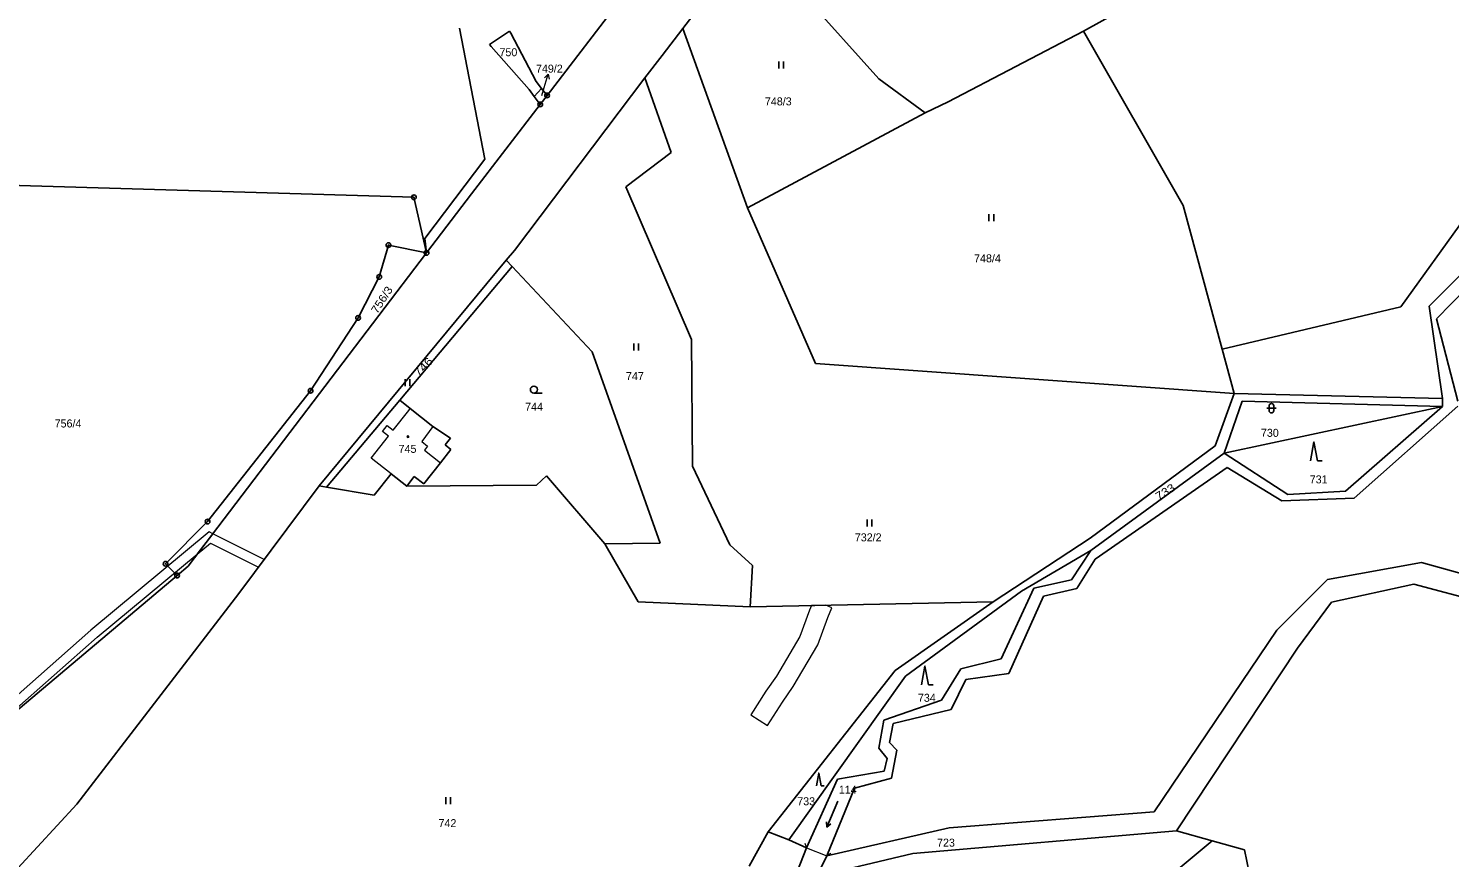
# Model space of a CAD drawing. Extents: x -727701 to -724405, y -960481 to -957284.
# Drawn here: x -726194 to -725892.1, y -958088.6 to -957912.5 of the extents above; entities that cross this region are included whole.
import ezdxf
from ezdxf.enums import TextEntityAlignment as Align

# ---------------------------------------------------------------- set-up
doc = ezdxf.new("R2010")
doc.units = 0
doc.header["$LTSCALE"] = 0.68
for name, color, linetype, lineweight in [('1', 7, 'Continuous', 25), ('13', 7, 'Continuous', 13), ('3', 7, 'Continuous', 25), ('4', 7, 'Continuous', 13), ('5', 7, 'Continuous', 25), ('7', 7, 'Continuous', 13), ('8', 7, 'Continuous', 25)]:
    doc.layers.add(name, color=color, linetype=linetype, lineweight=lineweight)
doc.layers.add('2', color=7, linetype='Continuous')

msp = doc.modelspace()

# ---------------------------------------------------------------- linework, layer by layer
at = {"layer": '1'}
for p, q in [((-726083.8, -957926.72), (-726042.74, -957873.32)), ((-725969.82, -957913.07), (-725930.41, -957891.06)), ((-726054.99, -957912.52), (-726040.19, -957893.25)), ((-726013.3, -957923.18), (-726040.19, -957893.25)), ((-726097, -957940.27), (-726102.4, -957912.45)), ((-726059.35, -957918.2), (-726054.99, -957912.52)), ((-726041.22, -957950.59), (-726054.99, -957912.52)), ((-726096.01, -957915.87), (-726091.76, -957913.04)), ((-726091.76, -957913.04), (-726091.5, -957913.52)), ((-726091.5, -957913.52), (-726086.14, -957923.75)), ((-725998.59, -957928.06), (-725969.82, -957913.07)), ((-725948.65, -957950.09), (-725969.82, -957913.07)), ((-726095.7, -957916.34), (-726096.01, -957915.87)), ((-726087.61, -957925.46), (-726095.7, -957916.34)), ((-726063, -957923), (-726059.35, -957918.2)), ((-726090.73, -957959.65), (-726063, -957923)), ((-726086.14, -957923.75), (-726084.98, -957925.28)), ((-726057.42, -957938.87), (-726063, -957923)), ((-726003.5, -957930.42), (-726013.3, -957923.18)), ((-726086.51, -957926.92), (-726087.61, -957925.46)), ((-726084.98, -957925.28), (-726086.51, -957926.92)), ((-726085.25, -957928.62), (-726086.51, -957926.92)), ((-726083.8, -957926.72), (-726085.25, -957928.62)), ((-726084.98, -957925.28), (-726083.8, -957926.72)), ((-726085.25, -957928.62), (-726099.85, -957947.6)), ((-726003.5, -957930.42), (-726041.22, -957950.59)), ((-725998.59, -957928.06), (-726003.5, -957930.42)), ((-726067.08, -957946.15), (-726057.42, -957938.87)), ((-726109.77, -957957.13), (-726097, -957940.27)), ((-726204.42, -957945.58), (-726112.08, -957948.36)), ((-726112.08, -957948.36), (-726109.41, -957960.16)), ((-726099.85, -957947.6), (-726109.41, -957960.16)), ((-726053.09, -957978.59), (-726067.08, -957946.15)), ((-726041.22, -957950.59), (-726026.78, -957983.68)), ((-725940.36, -957980.64), (-725948.65, -957950.09)), ((-725902.42, -957971.61), (-725888.74, -957952.67)), ((-726109.41, -957960.16), (-726109.77, -957957.13)), ((-726109.41, -957960.16), (-726160.05, -958026.69)), ((-726117.51, -957958.5), (-726119.45, -957965.25)), ((-726109.41, -957960.16), (-726117.51, -957958.5)), ((-726090.73, -957959.65), (-726092.46, -957961.74)), ((-725896.43, -957971.51), (-725884.9, -957959.98)), ((-726092.46, -957961.74), (-726132.25, -958009.67)), ((-726115.1, -957991.46), (-726091.22, -957963.06)), ((-726092.46, -957961.74), (-726091.22, -957963.06)), ((-726091.22, -957963.06), (-726074.22, -957981.19)), ((-725894.85, -957974.2), (-725883.57, -957962.64)), ((-726119.45, -957965.25), (-726123.94, -957973.97)), ((-725902.42, -957971.61), (-725940.36, -957980.64)), ((-725893.53, -957991.12), (-725896.43, -957971.51)), ((-726123.94, -957973.97), (-726134.05, -957989.44)), ((-725890.33, -957991.63), (-725894.85, -957974.2)), ((-726052.9, -958005.48), (-726053.09, -957978.59)), ((-726074.22, -957981.19), (-726059.78, -958021.83)), ((-725937.8, -957990.06), (-725940.36, -957980.64)), ((-726026.78, -957983.68), (-725937.8, -957990.06)), ((-726134.05, -957989.44), (-726155.91, -958017.23)), ((-725941.85, -958001.15), (-725937.8, -957990.06)), ((-725937.8, -957990.06), (-725893.53, -957991.12)), ((-725893.54, -957992.8), (-725893.53, -957991.12)), ((-726130.65, -958009.95), (-726115.1, -957991.46)), ((-726112.85, -957993.25), (-726115.1, -957991.46)), ((-726108.08, -957997.02), (-726112.85, -957993.25)), ((-725939.98, -958002.68), (-725936.1, -957991.65)), ((-725939.98, -958002.68), (-725893.54, -957992.8)), ((-725936.1, -957991.65), (-725893.54, -957992.8)), ((-725914.18, -958010.81), (-725893.54, -957992.8)), ((-725912.35, -958012.26), (-725890.34, -957992.75)), ((-726104.28, -957999.5), (-726108.08, -957997.02)), ((-726105.46, -958000.95), (-726104.28, -957999.5)), ((-726106.44, -958004.74), (-726104.23, -958001.95)), ((-726104.23, -958001.95), (-726105.46, -958000.95)), ((-725968.4, -958020.75), (-725941.85, -958001.15)), ((-725968.25, -958023.35), (-725939.98, -958002.68)), ((-725939.98, -958002.68), (-725926.44, -958011.51)), ((-726110.01, -958009.25), (-726106.44, -958004.74)), ((-726044.94, -958022.18), (-726052.9, -958005.48)), ((-725967.38, -958025.19), (-725939.28, -958005.73)), ((-725939.28, -958005.73), (-725927.73, -958012.86)), ((-726120.54, -958011.63), (-726116.94, -958007.08)), ((-726116.94, -958007.08), (-726113.61, -958009.71)), ((-726113.61, -958009.71), (-726112, -958007.68)), ((-726112, -958007.68), (-726110.01, -958009.25)), ((-726086.04, -958009.52), (-726083.92, -958007.55)), ((-726071.52, -958021.98), (-726083.92, -958007.55)), ((-726132.25, -958009.67), (-726149.3, -958032.49)), ((-726132.25, -958009.67), (-726130.65, -958009.95)), ((-726130.65, -958009.95), (-726120.54, -958011.63)), ((-726113.61, -958009.71), (-726086.04, -958009.52)), ((-725927.73, -958012.86), (-725912.35, -958012.26)), ((-725926.44, -958011.51), (-725914.18, -958010.81)), ((-726155.91, -958017.23), (-726164.85, -958026.2)), ((-725989, -958034.25), (-725968.4, -958020.75)), ((-726059.78, -958021.83), (-726071.52, -958021.98)), ((-726071.52, -958021.98), (-726064.42, -958034.27)), ((-726040.17, -958026.54), (-726044.94, -958022.18)), ((-725968.25, -958023.35), (-725983.04, -958032.05)), ((-725968.25, -958023.35), (-725972.38, -958029.64)), ((-726164.85, -958026.2), (-726162.41, -958028.69)), ((-726162.41, -958028.69), (-726160.05, -958026.69)), ((-726040.64, -958035.34), (-726040.17, -958026.54)), ((-725971.27, -958031.48), (-725967.38, -958025.19)), ((-725897.99, -958025.9), (-725917.98, -958029.56)), ((-725864.08, -958035.53), (-725897.99, -958025.9)), ((-726162.41, -958028.69), (-726197.08, -958057.94)), ((-725972.38, -958029.64), (-725980.35, -958031.35)), ((-725917.98, -958029.56), (-725928.75, -958040.32)), ((-725917.12, -958034.35), (-725899.62, -958030.56)), ((-725899.62, -958030.56), (-725867.81, -958038.93)), ((-726149.3, -958032.49), (-726183.72, -958077.25)), ((-725983.04, -958032.05), (-726007.63, -958050.06)), ((-725980.35, -958031.35), (-725987.31, -958046.38)), ((-725978.35, -958033.05), (-725985.7, -958049.5)), ((-725971.27, -958031.48), (-725978.35, -958033.05)), ((-726064.42, -958034.27), (-726040.64, -958035.34)), ((-726040.64, -958035.34), (-725989, -958034.25)), ((-725989, -958034.25), (-726009.88, -958048.87)), ((-725924.39, -958044.11), (-725917.12, -958034.35)), ((-725928.75, -958040.32), (-725954.85, -958078.87)), ((-725950.1, -958082.95), (-725924.39, -958044.11)), ((-725995.87, -958048.5), (-726000.01, -958055.15)), ((-725987.31, -958046.38), (-725995.87, -958048.5)), ((-726009.88, -958048.87), (-726036.81, -958083.12)), ((-726007.63, -958050.06), (-726032.4, -958084.87)), ((-725994.82, -958050.81), (-725997.92, -958057.14)), ((-725985.7, -958049.5), (-725994.82, -958050.81)), ((-726000.01, -958055.15), (-726012.24, -958059.43)), ((-725997.92, -958057.14), (-726010.24, -958060.15)), ((-726012.24, -958059.43), (-726013.34, -958065.36)), ((-726010.24, -958060.15), (-726011.02, -958064.15)), ((-726013.34, -958065.36), (-726011.57, -958067.59)), ((-726011.02, -958064.15), (-726009.5, -958065.82)), ((-726009.5, -958065.82), (-726010.6, -958071.75)), ((-726011.57, -958067.59), (-726012.2, -958070.23)), ((-726022.12, -958071.95), (-726028.71, -958086.53)), ((-726012.2, -958070.23), (-726022.12, -958071.95)), ((-726010.6, -958071.75), (-726018.51, -958073.86)), ((-726018.51, -958073.86), (-726024.39, -958088.24)), ((-726183.72, -958077.25), (-726206.6, -958101.98)), ((-725998.34, -958082.32), (-725954.85, -958078.87)), ((-726036.81, -958083.12), (-726040.87, -958090.42)), ((-726036.81, -958083.12), (-726032.4, -958084.87)), ((-726032.4, -958084.87), (-726028.71, -958086.53)), ((-725998.34, -958082.32), (-726024.39, -958088.24)), ((-725950.1, -958082.95), (-726006.06, -958087.73)), ((-725950.1, -958082.95), (-725942.48, -958085.07)), ((-726028.71, -958086.53), (-726032.04, -958095.01)), ((-726006.06, -958087.73), (-726018.93, -958090.76)), ((-725942.48, -958085.07), (-725954.39, -958094.93)), ((-725942.48, -958085.07), (-725935.63, -958086.98)), ((-725935.63, -958086.98), (-725934.15, -958094.15)), ((-726024.39, -958088.24), (-726028.5, -958096.53))]:
    msp.add_line(p, q, dxfattribs=at)
at = {"layer": '13'}
for points in [[(-726200.58, -958057.82), (-726197.66, -958057.92), (-726179.4, -958041.82), (-726158.11, -958024.15), (-726154.82, -958019.82), (-726155.57, -958019.44), (-726180.7, -958040.3)], [(-726158.11, -958024.15), (-726155.3, -958021.81), (-726145.14, -958026.92), (-726143.92, -958025.29), (-726154.82, -958019.82)], [(-726028.06, -958036.02), (-726030.12, -958041.63), (-726035.07, -958050.07), (-726037.29, -958053.29), (-726040.51, -958058.32), (-726036.97, -958060.58), (-726033.79, -958055.61), (-726031.51, -958052.29), (-726026.3, -958043.41), (-726024.16, -958037.58), (-726023.29, -958035.59), (-726024.6, -958035), (-726027.65, -958035.07)]]:
    msp.add_lwpolyline(points, close=True, dxfattribs=at)
at = {"layer": '3'}
for p, q in [((-726034.541, -957920.98), (-726034.541, -957919.48)), ((-726033.54, -957920.98), (-726033.54, -957919.48)), ((-725989.911, -957953.44), (-725989.911, -957951.94)), ((-725988.91, -957953.44), (-725988.91, -957951.94)), ((-726065.351, -957980.93), (-726065.351, -957979.43)), ((-726064.35, -957980.93), (-726064.35, -957979.43)), ((-726113.951, -957988.47), (-726113.951, -957986.97)), ((-726112.95, -957988.47), (-726112.95, -957986.97)), ((-726086.593, -957989.95), (-726084.843, -957989.95)), ((-725930.911, -957993.151), (-725928.909, -957993.151)), ((-725930.411, -957992.651), (-725930.411, -957993.652)), ((-725929.409, -957993.652), (-725929.409, -957992.651)), ((-725920.13, -958004.3), (-725919.134, -958004.3)), ((-726015.811, -958018.28), (-726015.811, -958016.78)), ((-726014.81, -958018.28), (-726014.81, -958016.78)), ((-726002.77, -958051.93), (-726001.774, -958051.93)), ((-726105.291, -958077.25), (-726105.291, -958075.75)), ((-726104.29, -958077.25), (-726104.29, -958075.75)), ((-726025.588, -958073.34), (-726024.92, -958073.34)), ((-726024.357, -958082.124), (-726024.437, -958081.029))]:
    msp.add_line(p, q, dxfattribs=at)
for points in [[(-725920.13, -958004.3), (-725920.88, -958000.3), (-725921.63, -958004.3)], [(-726002.77, -958051.93), (-726003.52, -958047.93), (-726004.27, -958051.93)], [(-726025.588, -958073.34), (-726026.09, -958070.66), (-726026.592, -958073.34)], [(-726022.012, -958076.601), (-726024.357, -958082.124), (-726023.513, -958081.42)]]:
    msp.add_lwpolyline(points, dxfattribs=at)
msp.add_circle((-726086.5929, -957989.1998), 0.75, dxfattribs=at)
for centre, start, end in [((-725929.91, -957992.6509), 0, 180), ((-725929.91, -957993.6509), 180, 359.98789)]:
    msp.add_arc(centre, 0.5, start, end, dxfattribs=at)
at = {"layer": '4'}
for p, q in [((-726116.48, -957997.84), (-726113.18, -957993.67)), ((-726113.18, -957993.67), (-726112.85, -957993.25)), ((-726118.74, -957998.12), (-726117.74, -957996.85)), ((-726117.74, -957996.85), (-726116.48, -957997.84)), ((-726108.08, -957997.02), (-726110.39, -958000.25)), ((-726121.15, -958003.75), (-726117.49, -957999.12)), ((-726117.49, -957999.12), (-726118.74, -957998.12)), ((-726110.39, -958000.25), (-726109.18, -958001.2)), ((-726109.18, -958001.2), (-726109.84, -958002.05)), ((-726109.84, -958002.05), (-726106.44, -958004.74)), ((-726116.94, -958007.08), (-726121.15, -958003.75)), ((-726029.002, -958085.573), (-726028.71, -958086.529)), ((-726028.71, -958086.53), (-726024.39, -958088.24)), ((-726023.541, -958087.71), (-726024.389, -958088.24))]:
    msp.add_line(p, q, dxfattribs=at)
at = {"layer": '5'}
msp.add_circle((-726113.3268, -957999.1892), 0.175, dxfattribs=at)
at = {"layer": '7'}
msp.add_line((-726083.543, -957922.17), (-726084.314, -957922.981), dxfattribs=at)
msp.add_lwpolyline([(-726084.94, -957926.73), (-726084.42, -957925.04), (-726083.543, -957922.17), (-726083.357, -957923.274)], dxfattribs=at)
at = {"layer": '8'}
for centre, radius in [((-726083.8, -957926.7199), 0.5), ((-726083.8, -957926.7199), 0.0303), ((-726085.25, -957928.6199), 0.5), ((-726085.25, -957928.6199), 0.0303), ((-726112.08, -957948.3599), 0.5), ((-726112.08, -957948.3599), 0.0303), ((-726117.51, -957958.4999), 0.5), ((-726117.51, -957958.4999), 0.0303), ((-726109.41, -957960.1599), 0.5), ((-726109.41, -957960.1599), 0.0303), ((-726119.45, -957965.2499), 0.5), ((-726119.45, -957965.2499), 0.0303), ((-726123.94, -957973.9699), 0.5), ((-726123.94, -957973.9699), 0.0303), ((-726134.05, -957989.4399), 0.5), ((-726134.05, -957989.4399), 0.0303), ((-726155.91, -958017.2299), 0.5), ((-726155.91, -958017.2299), 0.0303), ((-726164.85, -958026.1999), 0.5), ((-726164.85, -958026.1999), 0.0303), ((-726162.41, -958028.6899), 0.5), ((-726162.41, -958028.6899), 0.0303)]:
    msp.add_circle(centre, radius, dxfattribs=at)

# ---------------------------------------------------------------- texts
at = {"layer": '2'}
for s, p in [('750', (-726092.019, -957918.395)), ('749/2', (-726083.31, -957921.875)), ('756/4', (-726185.57, -957997.245))]:
    msp.add_text(s, height=1.7, dxfattribs=at).set_placement(p, align=Align.CENTER)
for s, p in [('748/3', (-726037.52, -957928.835)), ('748/4', (-725993.08, -957962.165)), ('747', (-726067.04, -957987.195)), ('744', (-726088.46, -957993.695)), ('730', (-725932.14, -957999.235)), ('745', (-726115.34, -958002.635)), ('731', (-725921.77, -958009.125)), ('732/2', (-726018.42, -958021.435)), ('734', (-726005.01, -958055.515)), ('733', (-726030.65, -958077.495)), ('114', (-726021.81, -958075.035)), ('742', (-726106.86, -958082.145)), ('723', (-726000.95, -958086.285))]:
    msp.add_text(s, height=1.7, dxfattribs=at).set_placement(p)
at = {"layer": '2', "width": 1.1}
msp.add_text('756/3', height=1.7, rotation=57, dxfattribs=at).set_placement((-726118.1804, -957970.5959), align=Align.CENTER)
at = {"layer": '2'}
for s, rotation, width, p in [('746', 46, 1.2, (-726111.064, -957986.615)), ('733', 32, 1.15, (-725953.884, -958012.8))]:
    msp.add_text(s, height=1.7, rotation=rotation, dxfattribs=dict(at, width=width)).set_placement(p)

doc.saveas('drawing.dxf')
